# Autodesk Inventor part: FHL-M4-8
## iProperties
FINISH: PASSIVATE
d3: 2.500 mm
head_diameter: 9.600 mm
Author: KD
Revision Number: 1
Shininess: 64.0
Angle Display Precision: 2
Document Length Units: 11269
Document Angle Units: 11284
Document Time Units: 11279
Document Mass Units: 11290
Document Length Units Precision: 3
Document Angle Units Precision: 2
Compacted: True
PropertySet Name: _Private Model Information
Created: 2002-07
Part Number: FHL-M4-8
Material: Steel, High Strength Low Alloy
Description: STUD, SELF CLINCH,  M4x0.7 X 8
Vendor: PENN ENG & MFG
Document SubType Name: Modeling
Designer: KD
Control State: 0
Master: False
Checked Out: False
PropertySet Name: Design Tracking Control
Density: 0.0
Volumn: 0.0
Area: 0.0
PropertySet Name: Model Information
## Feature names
1. Shank [Extrusion]
2. Head [Extrusion]
3. Chamfer1
